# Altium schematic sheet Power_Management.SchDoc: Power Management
size A4; Author: Ph.A; SheetNumber: 5; SheetTotal: 6
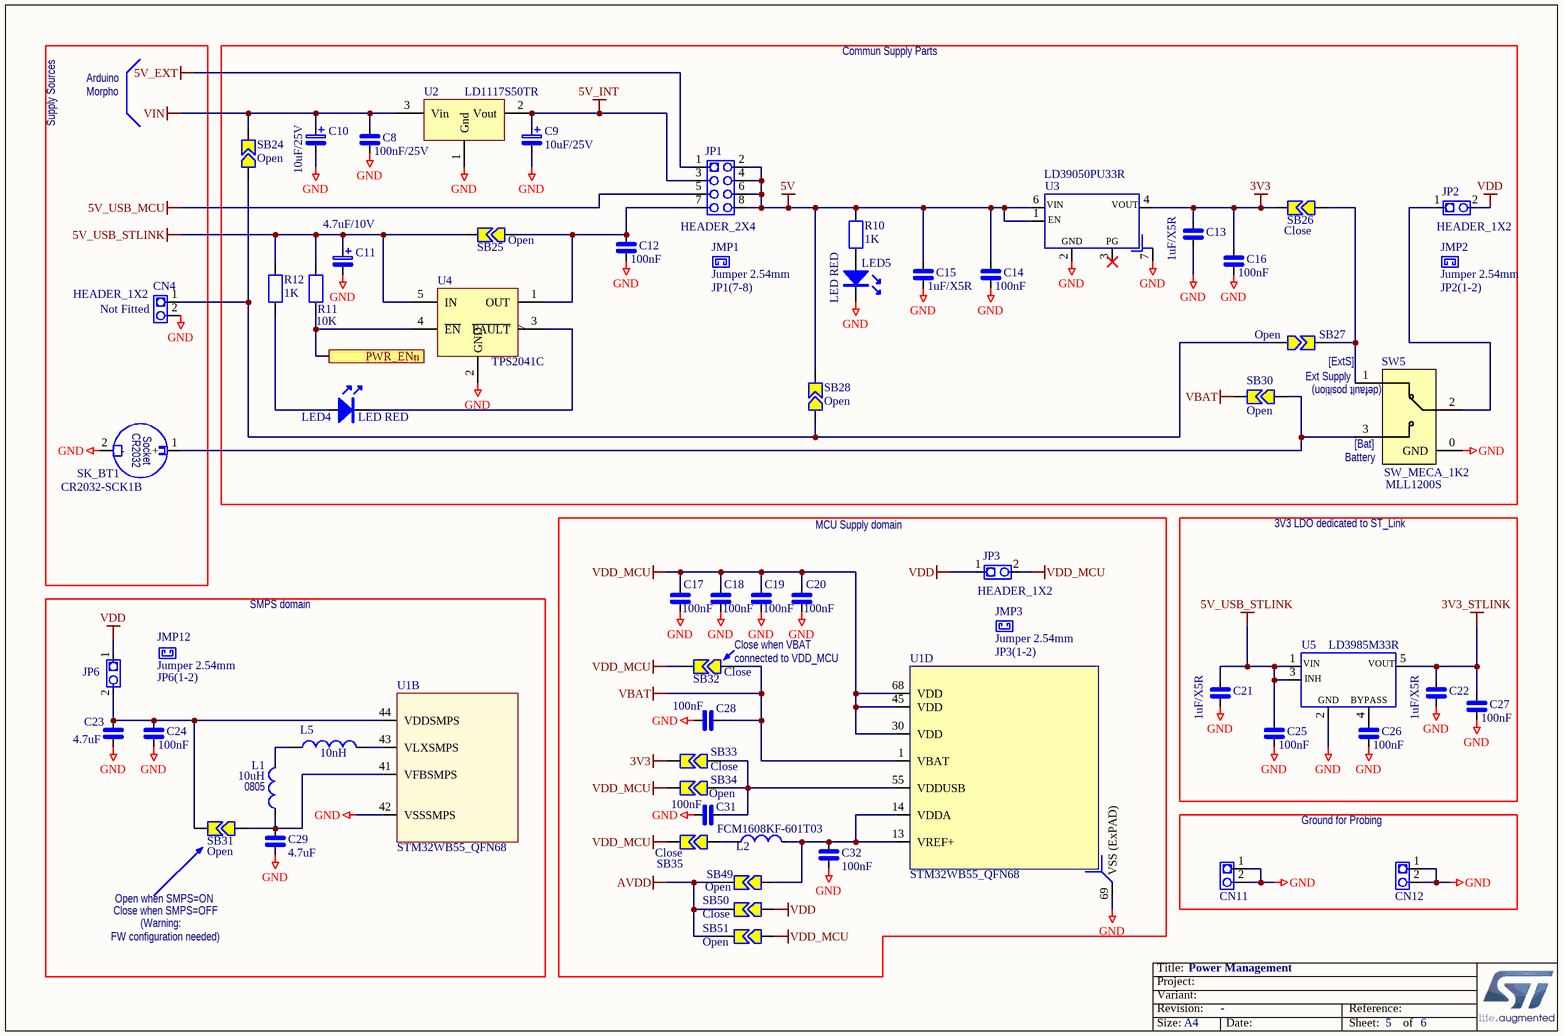
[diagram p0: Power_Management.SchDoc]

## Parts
C8  100nF/25V  [0402_CAP_NPOL]
C9  10uF/25V  [1210_CAP_POL]
C10  10uF/25V  [1210_CAP_POL]
C11  4.7uF/10V  [1210_CAP_POL]
C12  100nF  [0402_CAP_NPOL]
C13  1uF/X5R  [0603_CAP_NPOL]
C14  100nF  [0402_CAP_NPOL]
C15  1uF/X5R  [0603_CAP_NPOL]
C16  100nF  [0402_CAP_NPOL]
C17  100nF  [0402_CAP_NPOL]
C18  100nF  [0402_CAP_NPOL]
C19  100nF  [0402_CAP_NPOL]
C20  100nF  [0402_CAP_NPOL]
C21  1uF/X5R  [0603_CAP_NPOL]
C22  1uF/X5R  [0603_CAP_NPOL]
C23  4.7uF  [0402_CAP_NPOL]
C24  100nF  [0402_CAP_NPOL]
C25  100nF  [0402_CAP_NPOL]
C26  100nF  [0402_CAP_NPOL]
C27  100nF  [0402_CAP_NPOL]
C28  100nF  [0402_CAP_NPOL]
C29  4.7uF  [0402_CAP_NPOL]
C31  100nF  [0402_CAP_NPOL]
C32  100nF  [0402_CAP_NPOL]
CN4  HEADER_1X2  Fitted: Not Fitted  [Header NF 1x2x2.54 TH]
CN11  HEADER_1X2  [Header M 1x2x2.54 TH V]  (value not drawn)
CN12  HEADER_1X2  [Header M 1x2x2.54 TH V]  (value not drawn)
JMP1  Jumper 2.54mm  Default: JP1(7-8)  [Jumper 2.54mm BLACK]
JMP2  Jumper 2.54mm  Default: JP2(1-2)  [Jumper 2.54mm BLACK]
JMP3  Jumper 2.54mm  default: JP3(1-2)  [Jumper 2.54mm BLACK]
JMP12  Jumper 2.54mm  default: JP6(1-2)  [Jumper 2.54mm BLACK]
JP1  HEADER_2X4  [Header M 2x4x2.54 TH V]
JP2  HEADER_1X2  [Header M 1x2x2.54 TH V]
JP3  HEADER_1X2  [Header M 1x2x2.54 TH V]
JP6  HEADER_1X2  [Header M 1x2x2.54 TH V]  (value not drawn)
L1  10uH  [0805_COIL]
L2  FCM1608KF-601T03  [0603_COIL]
L5  value 10nH  [IND_0402_MURATA_LQW15AN_H0P5]  (hidden comment: Inductor)
LED4  LED RED  [0603_LED_RED]
LED5  LED RED  [0603_LED_RED]
R10  1K  [0402_RES]
R11  10K  [0402_RES]
R12  1K  [0402_RES]
SB24  Open  [SB-tiny]
SB25  Open  [SB-tiny]
SB26  Close  [SB-tiny]
SB27  Open  [SB-tiny]
SB28  Open  [SB-tiny]
SB30  Open  [SB-tiny]
SB31  Open  [SB-tiny]
SB32  Close  [SB-tiny]
SB33  Close  [SB-tiny]
SB34  Open  [SB-tiny]
SB35  Close  [SB-tiny]
SB49  Open  [SB-tiny]
SB50  Close  [SB-tiny]
SB51  Open  [SB-tiny]
SK_BT1  CR2032-SCK1B  [CR2032-SCK1]
SW5  SW_MECA_1K2  value MLL1200S  [SWI_SPDT-RA_TE-CONNECTIVITY_MLL1200S_1P2T]
U1  STM32WB55_QFN68  [VFQFPN68_8x8x0.1_p0.4]  (parts B,D of 5)
U2  LD1117S50TR  [SOT223_SC73_A]
U3  LD39050PU33R  [DFN6 3x3mm]
U4  TPS2041C  [MOS_SOT23-5L]
U5  LD3985M33R  [SOT23-5]

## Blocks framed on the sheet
3V3 LDO dedicated to ST_Link: C21 C22 C25-C27 U5
Ground for Probing: CN11 CN12

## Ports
PWR_ENn

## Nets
3V3: C13.1 C16.1 SB26.2 SB33.2 U3.4(VOUT)
3V3_STLINK: C22.1 C27.1 U5.5(VOUT)
5V: C14.1 C15.1 JP1.2 JP1.4 JP1.6 JP1.8 R10.1 SB28.2 U3.1(EN) U3.6(VIN)
5V_EXT: JP1.1
5V_INT: C9.1 JP1.3 U2.2(Vout)
5V_USB_MCU: JP1.5
5V_USB_STLINK: C11.1 C21.1 C25.1 R11.1 R12.1 SB25.2 U4.5(IN) U5.1(VIN) U5.3(CE)
AVDD: SB49.2 SB50.2 SB51.2
GND: C8.2 C9.2 C10.2 C11.2 C12.2 C13.2 C14.2 C15.2 C16.2 C17.2 C18.2 C19.2 C20.2 C21.2 C22.2 C23.2 C24.2 C25.2 C26.2 C27.2 C28.2 C29.2 C31.2 C32.2 CN4.2 CN11.1 CN11.2 CN12.1 CN12.2 LED5.K SK_BT1.2(-) SW5.0(GND) U1.42(VSSSMPS) U1.69(VSS_(ExPAD)) U2.1(Gnd) U3.2(VSS) U3.7 U4.2(GND) U5.2(VSS)
VBAT: C28.1 SB30.2 SB32.1 U1.1(VBAT)
VDD: JP2.2 JP3.1 JP6.1 SB50.1
VDD_MCU: C17.1 C18.1 C19.1 C20.1 JP3.2 SB32.2 SB34.2 SB35.2 SB51.1 U1.30(VDD) U1.45(VDD) U1.68(VDD)
VIN: C8.1 C10.1 SB24.2 U2.3(Vin)
PWR_ENn: R11.2 U4.4(~{EN}) ; port PWR_ENn
NetC12_1: C12.1 JP1.7 SB25.1 U4.1(OUT)
NetC23_1: C23.1 C24.1 JP6.2 SB31.2 U1.44(VDDSMPS)
NetC26_1: C26.1 U5.4(BYPASS)
NetC29_1: C29.1 L1.1 SB31.1 U1.41(VFBSMPS)
NetC31_1: C31.1 SB33.1 SB34.1 U1.55(VDDUSB)
NetC32_1: C32.1 L2.2 SB49.1 U1.13(VREF+) U1.14(VDDA)
NetCN4_1: CN4.1 SB24.1 SB27.1 SB28.1
NetJP2_1: JP2.1 SW5.2
NetL1_2: L1.2 L5.1
NetL2_1: L2.1 SB35.1
NetL5_2: L5.2 U1.43(VLXSMPS)
NetLED4_A: LED4.A R12.2
NetLED4_K: LED4.K U4.3(~{FAULT})
NetLED5_A: LED5.A R10.2
NetSB26_1: SB26.1 SB27.2 SW5.1
NetSB30_1: SB30.1 SK_BT1.1(+) SW5.3

Not connected (* = marked no-connect by the designer): U3 3(PG)*

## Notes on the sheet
- Arduino
- Morpho
- Commun Supply Parts
- Supply Sources
- Ext Supply
- [ExtS]
- (default position)
- (near SW5) [Bat]
- (near SW5) Battery
- MCU Supply domain
- SMPS domain
- (near SB32) Close when VBAT
- (near SB32) connected to VDD_MCU
- (near L1) 0805
- Close when SMPS=OFF
- Open when SMPS=ON
- FW configuration needed)
- (Warning:

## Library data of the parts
C8 C12-C29 C31 C32 = CAP_NPOL: Capacitor_not polarized
C9-C11 = CAP_POL: Condensateur_polarise
JP2 JP3 JP6 = HEADER_1X2_L
L1 = IND_74479777310A: Coil Wurtz 10uH ref: 74479777310A
L2 = IND_FCM1608KF-601T03
L5 = MCD-02063: inductor, 10nH +-2%, 100mA max,1.3 ohm DC max, Q min = 13,0402; Manufacturer_Part_Number: LQP15MN10NG02; Manufacturer: MURATA; ECCN_US: EAR99; ECCN_EU: NEC; Provided_By: SUBCO; Order_Code_RS: 167-3827
LED4 LED5 = LED: Light-Emitting Diode
R10-R12 = RES: Resistor
SB24-SB28 SB30-SB35 SB49-SB51 = Strap2: Solder Jumper; Solder: YES
SW5 = MCD-02081: SPDT RA SMT SLIDE SWITCH; Part_Type: Connector; Manufacturer: TE_Connectivity; ECCN_US: EAR99; ECCN_EU: NEC; Provided_By: SUBCO
U1 = STM32WBxx_QFN68
U2 = LD1117S50TR: IC REG LDO 5V 0.8A SOT223; Manuf_1: STM; ECCN_US/EU: EAR99/NEC; Ref St: 9176133; Fitted: YES
U3 = LD39050PU33R: 3.3V voltage regulator 500mA
U4 = MCD-01785: 5V Power Switch, 0.85A, RDSon 130mOhm max, with active low enable pin; Part_Type: IC; Manufacturer_Part_Number: TPS2041CDBVT; Manufacturer: TEXAS INSTRUMENTS; ECCN_US: EAR99; ECCN_EU: NEC; Provided_By: SUBCO
U5 = LD3985M33R: 3.3V low drop voltage regulator; Manufacturer: STMicroelectronics; Isortie max: 550mA; V entrée max: 6V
